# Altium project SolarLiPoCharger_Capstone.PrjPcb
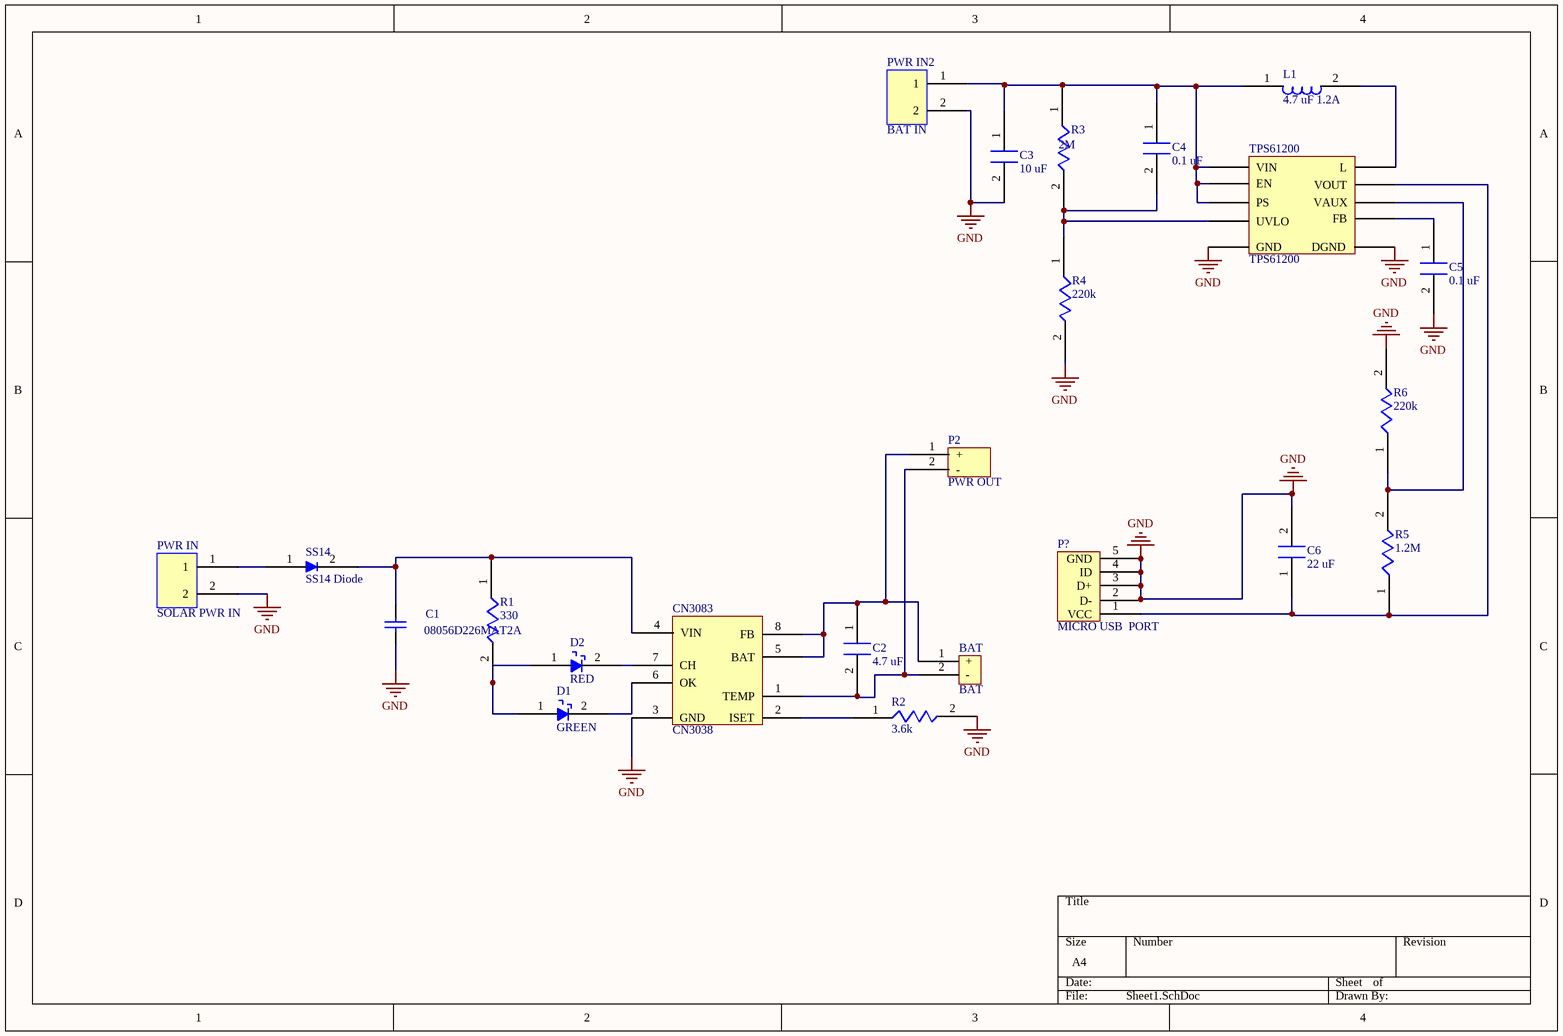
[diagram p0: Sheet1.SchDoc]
1 sheet, 23 parts. Net scope: global (net labels, ports and power ports of the same name join across sheets).
Board file: solarlipocharger.PcbDoc

## Sheet Sheet1.SchDoc
size A4

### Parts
BAT  BAT  [PWR]
C1  08056D226MAT2A  [CAPC2013X140X50LL20T25]
C2  4.7 uF  [CAPACITOR 0402]
C3  10 uF  [CAPACITOR 0805]
C4  0.1 uF  [CAPACITOR 0402]
C5  0.1 uF  [CAPACITOR 0402]
C6  22 uF  [CAPACITOR 0805]
CN3083  CN3038  [CN3083]
D1  GREEN  [DIODE 0603]
D2  RED  [DIODE 0603]
L1  4.7 uF 1.2A  [LPS3015]
P2  PWR OUT  [PWR]
P?  MICRO USB  PORT  [MICRO USB OUT]
PWR_IN  SOLAR PWR IN  [PWR]
PWR_IN2  BAT IN  [PWR]
R1  330  [RESISTOR 0402]
R2  3.6k  [RESISTOR 0402]
R3  2M  [RESISTOR 0805]
R4  220k  [RESISTOR 0805]
R5  1.2M  [RESISTOR 0805]
R6  220k  [RESISTOR 0402]
SS14  SS14 Diode  [SS14]
TPS61200  TPS61200  [TPS61200]

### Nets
GND: C1.2 C3.2 C5.2 C6.2 CN3083.3(GND) P?.2(D-) P?.3(D+) P?.4(ID) P?.5(GND) PWR_IN.2 PWR_IN2.2 R2.2 R4.2 R6.2 TPS61200.4(DGND) TPS61200.9(GND)
NetBAT_1: BAT.1(+) C2.1 CN3083.5(BAT) CN3083.8(FB) P2.1(+)
NetBAT_2: BAT.2(-) C2.2 CN3083.1(TEMP) P2.2(-)
NetC1_1: C1.1 CN3083.4(VIN) R1.1 SS14.2
NetC3_1: C3.1 C4.1 L1.1 PWR_IN2.1 R3.1 TPS61200.5(VIN) TPS61200.6(EN) TPS61200.8(PS)
NetC4_2: C4.2 R3.2 R4.1 TPS61200.7(UVLO)
NetC5_1: C5.1 TPS61200.10(FB)
NetC6_1: C6.1 P?.1(VCC) R5.1 TPS61200.2(VOUT)
NetCN3083_2: CN3083.2(ISET) R2.1
NetCN3083_6: CN3083.6(OK) D1.2
NetCN3083_7: CN3083.7(CH) D2.2
NetD1_1: D1.1 D2.1 R1.2
NetL1_2: L1.2 TPS61200.3(L)
NetPWR_IN_1: PWR_IN.1 SS14.1
NetR5_2: R5.2 R6.1 TPS61200.1(VAUX)

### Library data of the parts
C1 = CMP-001-00083-1: AVX         08056D226MAT2A.            CERAMIC CAPACITOR, 22UF, 6.3V, X5R, 20%, 0805, FULL REEL; Dissipation Factor: 12.5%; Insulation Resistance: 10GR
C2 C4 C5 = Capacitor 0402
C3 C6 = Capacitor 0805
D1 D2 = Diode 0603
L1 = Inductor: LPS3015 - 222MRB
PWR_IN2 = SOLAR PWR IN
R1 R2 R6 = Resistor 0402
R3-R5 = Resistor 0805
